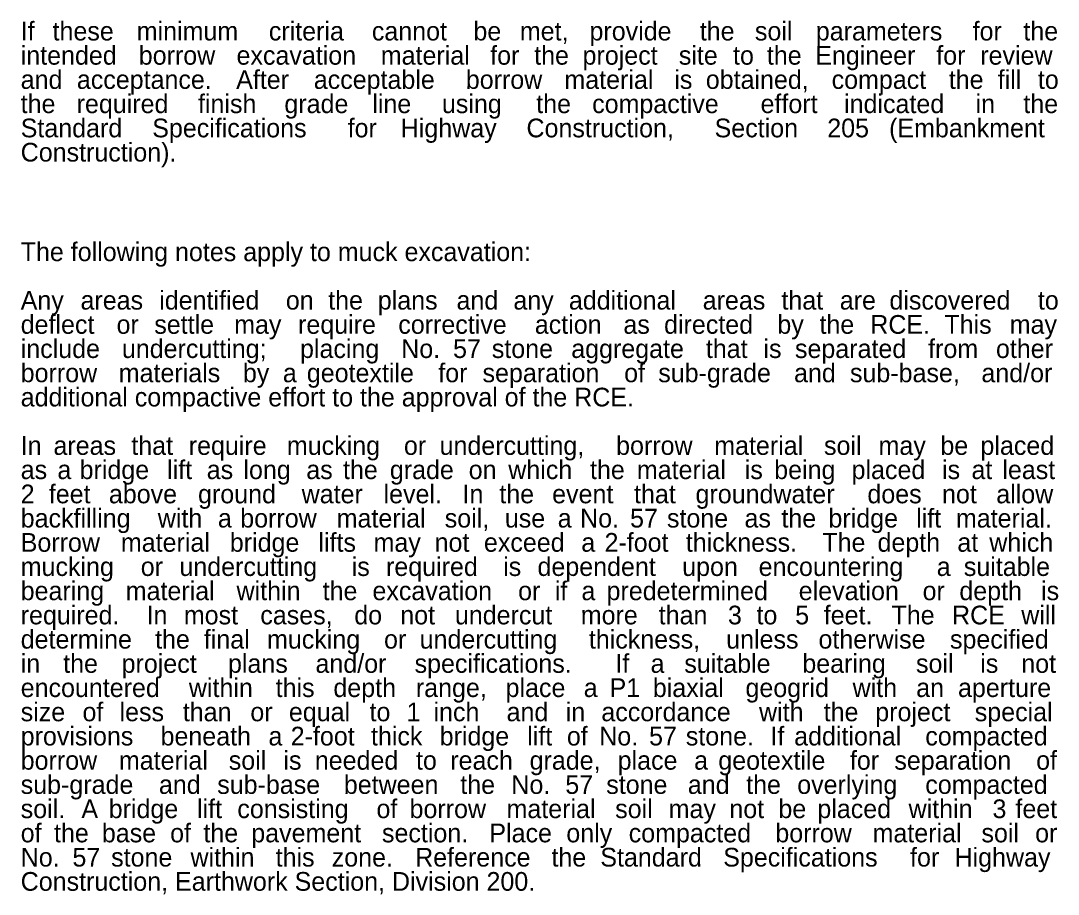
# Model space of a CAD drawing. Extents: x 4804 to 5434, y 4929 to 5221.
# Drawn here: x 5102.6 to 5179.4, y 5037.3 to 5101.9 of the extents above; entities that cross this region are included whole.
import ezdxf

# ---------------------------------------------------------------- set-up
doc = ezdxf.new("R2010")
doc.units = 0
doc.layers.add('RD_TX_RoadID', color=7, linetype='Continuous')

msp = doc.modelspace()

# ---------------------------------------------------------------- texts
at = {"layer": 'RD_TX_RoadID'}
for s, p in [('If ', (5102.645, 5100.425)), ('these ', (5105.003, 5100.425)), ('minimum ', (5111.231, 5100.425)), ('criteria ', (5121.007, 5100.425)), ('be ', (5136.149, 5100.425)), ('provide ', (5144.737, 5100.425)), ('the ', (5152.899, 5100.425)), ('soil ', (5156.977, 5100.425)), ('for ', (5173.09, 5100.425)), ('the ', (5176.845, 5100.425)), ('cannot ', (5128.632, 5100.425)), ('met, ', (5139.583, 5100.425)), ('parameters ', (5161.486, 5100.425)), ('intended ', (5102.645, 5098.633)), ('borrow ', (5111.383, 5098.633)), ('excavation ', (5118.617, 5098.633)), ('material ', (5129.292, 5098.633)), ('for ', (5137.387, 5098.633)), ('the ', (5140.643, 5098.633)), ('project ', (5144.223, 5098.633)), ('site ', (5151.349, 5098.633)), ('to ', (5155.359, 5098.633)), ('the ', (5157.863, 5098.633)), ('Engineer ', (5161.443, 5098.633)), ('for ', (5170.398, 5098.633)), ('review ', (5173.654, 5098.633)), ('and ', (5102.645, 5096.842)), ('acceptance. ', (5106.801, 5096.842)), ('After ', (5118.59, 5096.842)), (' acceptable ', (5123.82, 5096.842)), (' borrow ', (5135.07, 5096.842)), ('material ', (5142.88, 5096.842)), ('is ', (5151.013, 5096.842)), ('obtained, ', (5153.343, 5096.842)), ('compact ', (5162.656, 5096.842)), ('the ', (5171.326, 5096.842)), ('fill ', (5174.944, 5096.842)), ('to ', (5177.917, 5096.842)), ('the ', (5102.645, 5095.05)), ('required ', (5106.785, 5095.05)), ('finish ', (5115.763, 5095.05)), ('grade ', (5122.159, 5095.05)), ('line ', (5128.665, 5095.05)), ('using ', (5133.817, 5095.05)), ('the ', (5140.795, 5095.05)), ('compactive ', (5144.935, 5095.05)), ('effort ', (5157.396, 5095.05)), ('indicated ', (5163.576, 5095.05)), ('in ', (5173.305, 5095.05)), ('the ', (5176.844, 5095.05)), ('Standard ', (5102.645, 5093.258)), ('Specifications ', (5112.379, 5093.258)), ('for ', (5126.841, 5093.258)), ('Highway ', (5130.769, 5093.258)), ('Construction, ', (5140.073, 5093.258)), ('Section ', (5153.995, 5093.258)), ('205 ', (5162.331, 5093.258)), ('(Embankment ', (5166.907, 5093.258)), ('Construction).', (5102.645, 5091.466)), ('The following notes apply to muck excavation:', (5102.645, 5084.097)), ('Any ', (5102.645, 5080.513)), ('identified ', (5112.897, 5080.513)), ('the ', (5125.399, 5080.513)), ('plans ', (5129.072, 5080.513)), ('and ', (5134.896, 5080.513)), ('additional ', (5143.211, 5080.513)), ('that ', (5158.942, 5080.513)), ('discovered ', (5166.933, 5080.513)), ('areas ', (5107.071, 5080.513)), ('on ', (5122.264, 5080.513)), ('any ', (5139.107, 5080.513)), ('areas ', (5153.116, 5080.513)), ('are ', (5163.258, 5080.513)), ('to ', (5177.917, 5080.513)), ('deflect ', (5102.645, 5078.722)), ('or ', (5109.737, 5078.722)), ('settle ', (5112.531, 5078.722)), ('may ', (5118.441, 5078.722)), ('require ', (5123.171, 5078.722)), ('corrective ', (5130.587, 5078.722)), ('action ', (5140.691, 5078.722)), ('as ', (5147.246, 5078.722)), ('directed ', (5150.256, 5078.722)), ('by ', (5158.639, 5078.722)), ('the ', (5161.756, 5078.722)), ('RCE. ', (5165.516, 5078.722)), ('This ', (5170.998, 5078.722)), ('may ', (5175.834, 5078.722)), ('include ', (5102.645, 5076.93)), ('undercutting; ', (5110.134, 5076.93)), ('placing ', (5123.316, 5076.93)), ('No. ', (5130.805, 5076.93)), ('57 ', (5134.64, 5076.93)), ('stone ', (5137.509, 5076.93)), ('aggregate ', (5143.386, 5076.93)), ('that ', (5153.348, 5076.93)), ('is ', (5157.611, 5076.93)), ('separated ', (5159.942, 5076.93)), ('from ', (5169.797, 5076.93)), ('other ', (5174.814, 5076.93)), ('borrow ', (5102.645, 5075.138)), ('materials ', (5109.899, 5075.138)), ('by ', (5119.09, 5075.138)), ('geotextile ', (5123.82, 5075.138)), ('for ', (5133.546, 5075.138)), ('separation ', (5136.822, 5075.138)), ('of ', (5147.301, 5075.138)), ('sub-grade ', (5149.826, 5075.138)), ('and ', (5159.874, 5075.138)), ('sub-base, ', (5164.012, 5075.138)), ('and/or ', (5173.739, 5075.138)), ('a ', (5122.046, 5075.138)), ('additional compactive effort to the approval of the RCE. ', (5102.645, 5073.346)), ('In ', (5102.645, 5069.762)), ('that ', (5110.83, 5069.762)), ('require ', (5115.081, 5069.762)), ('mucking ', (5122.344, 5069.762)), ('undercutting, ', (5133.644, 5069.762)), ('borrow ', (5146.707, 5069.762)), ('material ', (5153.968, 5069.762)), ('soil ', (5162.091, 5069.762)), ('be ', (5170.706, 5069.762)), ('placed ', (5173.669, 5069.762)), ('areas ', (5105.07, 5069.762)), ('or ', (5131.004, 5069.762)), ('may ', (5166.129, 5069.762)), ('as ', (5102.645, 5067.971)), ('a ', (5105.363, 5067.971)), ('bridge ', (5107.005, 5067.971)), ('lift ', (5113.482, 5067.971)), ('as ', (5116.411, 5067.971)), ('long ', (5119.128, 5067.971)), ('as ', (5123.778, 5067.971)), ('the ', (5126.496, 5067.971)), ('grade ', (5129.963, 5067.971)), ('on ', (5135.797, 5067.971)), ('which ', (5138.728, 5067.971)), ('the ', (5144.776, 5067.971)), ('material ', (5148.244, 5067.971)), ('is ', (5156.227, 5067.971)), ('being ', (5158.406, 5067.971)), ('placed ', (5164.131, 5067.971)), ('is ', (5170.825, 5067.971)), ('at ', (5173.004, 5067.971)), ('least ', (5175.29, 5067.971)), ('2 ', (5102.645, 5066.179)), ('feet ', (5104.727, 5066.179)), ('above ', (5109.172, 5066.179)), ('ground ', (5115.769, 5066.179)), ('water ', (5123.437, 5066.179)), ('level. ', (5129.496, 5066.179)), ('In ', (5135.34, 5066.179)), ('the ', (5138.065, 5066.179)), ('event ', (5141.973, 5066.179)), ('that ', (5148.031, 5066.179)), ('groundwater ', (5152.583, 5066.179)), ('does ', (5165.303, 5066.179)), ('not ', (5170.824, 5066.179)), ('allow ', (5174.838, 5066.179)), ('backfilling ', (5102.645, 5064.387)), ('with ', (5112.789, 5064.387)), ('borrow ', (5118.893, 5064.387)), ('material ', (5126.028, 5064.387)), ('soil, ', (5134.025, 5064.387)), ('No. ', (5144.042, 5064.387)), ('57 ', (5147.739, 5064.387)), ('the ', (5158.939, 5064.387)), ('bridge ', (5162.42, 5064.387)), ('lift ', (5168.911, 5064.387)), ('material. ', (5171.853, 5064.387)), ('a ', (5117.237, 5064.387)), ('use ', (5138.474, 5064.387)), ('a ', (5142.387, 5064.387)), ('stone ', (5150.47, 5064.387)), ('as ', (5156.208, 5064.387)), ('Borrow ', (5102.645, 5062.595)), ('material ', (5110.06, 5062.595)), ('bridge ', (5118.121, 5062.595)), ('lifts ', (5124.677, 5062.595)), ('may ', (5128.758, 5062.595)), ('not ', (5133.274, 5062.595)), ('exceed ', (5136.926, 5062.595)), ('a ', (5144.129, 5062.595)), ('2-foot ', (5145.849, 5062.595)), ('thickness. ', (5151.864, 5062.595)), ('The ', (5161.967, 5062.595)), ('depth ', (5166.05, 5062.595)), ('at ', (5171.96, 5062.595)), ('which ', (5174.324, 5062.595)), ('mucking ', (5102.645, 5060.803)), ('or ', (5111.528, 5060.803)), ('undercutting ', (5114.391, 5060.803)), ('is ', (5127.139, 5060.803)), ('required ', (5129.68, 5060.803)), ('is ', (5138.348, 5060.803)), ('dependent ', (5140.889, 5060.803)), ('upon ', (5151.597, 5060.803)), ('encountering ', (5157.254, 5060.803)), ('a ', (5170.433, 5060.803)), ('suitable ', (5172.438, 5060.803)), ('bearing ', (5102.645, 5059.011)), ('material ', (5110.416, 5059.011)), ('within ', (5118.617, 5059.011)), ('the ', (5124.988, 5059.011)), ('excavation ', (5128.674, 5059.011)), ('if ', (5142.174, 5059.011)), ('predetermined ', (5146, 5059.011)), ('elevation ', (5160.219, 5059.011)), ('depth ', (5172.106, 5059.011)), ('is ', (5178.155, 5059.011)), ('or ', (5139.455, 5059.011)), ('a ', (5144.14, 5059.011)), ('or ', (5169.387, 5059.011)), ('required. ', (5102.645, 5057.22)), ('In ', (5111.959, 5057.22)), ('most ', (5114.717, 5057.22)), ('cases, ', (5120.377, 5057.22)), ('do ', (5127.329, 5057.22)), ('not ', (5130.732, 5057.22)), ('undercut ', (5134.778, 5057.22)), ('more ', (5144.091, 5057.22)), ('than ', (5149.86, 5057.22)), ('3 ', (5154.981, 5057.22)), ('to ', (5157.095, 5057.22)), ('5 ', (5159.96, 5057.22)), ('feet. ', (5162.074, 5057.22)), ('The ', (5167.088, 5057.22)), ('RCE ', (5171.566, 5057.22)), ('will ', (5176.689, 5057.22)), ('determine ', (5102.645, 5055.428)), ('the ', (5112.591, 5055.428)), ('final ', (5116.196, 5055.428)), ('mucking ', (5120.874, 5055.428)), ('or ', (5129.531, 5055.428)), ('undercutting ', (5132.168, 5055.428)), ('thickness, ', (5144.69, 5055.428)), ('unless ', (5154.852, 5055.428)), ('otherwise ', (5161.682, 5055.428)), ('specified ', (5171.413, 5055.428)), ('in ', (5102.645, 5053.636)), ('the ', (5105.788, 5053.636)), ('project ', (5110.113, 5053.636)), ('plans ', (5117.985, 5053.636)), ('and/or ', (5124.46, 5053.636)), ('specifications. ', (5131.795, 5053.636)), ('If ', (5146.652, 5053.636)), ('suitable ', (5151.756, 5053.636)), ('bearing ', (5160.488, 5053.636)), ('soil ', (5168.898, 5053.636)), ('is ', (5173.653, 5053.636)), ('a ', (5149.257, 5053.636)), ('not ', (5176.689, 5053.636)), ('encountered ', (5102.645, 5051.844)), ('within ', (5115.089, 5051.844)), ('this ', (5121.512, 5051.844)), ('depth ', (5125.786, 5051.844)), ('range, ', (5131.888, 5051.844)), ('place ', (5138.528, 5051.844)), ('a ', (5144.31, 5051.844)), ('P1 ', (5146.222, 5051.844)), ('biaxial ', (5149.424, 5051.844)), ('geogrid ', (5156.28, 5051.844)), ('with ', (5164.209, 5051.844)), ('an ', (5168.913, 5051.844)), ('aperture ', (5172.007, 5051.844)), ('size ', (5102.645, 5050.052)), ('of ', (5107.217, 5050.052)), ('less ', (5109.96, 5050.052)), ('than ', (5114.64, 5050.052)), ('or ', (5119.639, 5050.052)), ('equal ', (5122.49, 5050.052)), ('to ', (5128.459, 5050.052)), ('1 ', (5131.201, 5050.052)), ('inch ', (5133.193, 5050.052)), (' and ', (5138.086, 5050.052)), ('in ', (5142.979, 5050.052)), ('accordance ', (5145.615, 5050.052)), ('with ', (5157.282, 5050.052)), ('the ', (5162.066, 5050.052)), ('project ', (5165.884, 5050.052)), ('special ', (5173.248, 5050.052)), ('provisions ', (5102.645, 5048.261)), ('beneath ', (5112.995, 5048.261)), ('2-foot ', (5122.626, 5048.261)), ('thick ', (5128.567, 5048.261)), ('bridge ', (5133.65, 5048.261)), ('lift ', (5140.131, 5048.261)), ('of ', (5143.063, 5048.261)), ('No. ', (5145.458, 5048.261)), ('57 ', (5149.145, 5048.261)), ('If ', (5158.131, 5048.261)), ('additional ', (5159.882, 5048.261)), ('compacted ', (5169.585, 5048.261)), ('a ', (5120.981, 5048.261)), ('stone. ', (5151.866, 5048.261)), ('borrow ', (5102.645, 5046.469)), ('material ', (5109.913, 5046.469)), ('soil ', (5118.042, 5046.469)), ('is ', (5122.086, 5046.469)), ('needed ', (5124.411, 5046.469)), ('to ', (5131.895, 5046.469)), ('reach ', (5134.433, 5046.469)), ('grade, ', (5140.306, 5046.469)), ('place ', (5146.822, 5046.469)), ('a ', (5152.48, 5046.469)), ('geotextile ', (5154.268, 5046.469)), ('for ', (5164.007, 5046.469)), ('separation ', (5167.297, 5046.469)), ('of ', (5177.79, 5046.469)), ('sub-grade ', (5102.645, 5044.677)), ('and ', (5112.873, 5044.677)), ('sub-base ', (5117.19, 5044.677)), ('between ', (5126.559, 5044.677)), ('the ', (5135.175, 5044.677)), ('No. ', (5138.954, 5044.677)), ('57 ', (5142.948, 5044.677)), ('stone ', (5145.977, 5044.677)), ('and ', (5152.013, 5044.677)), ('the ', (5156.33, 5044.677)), ('overlying ', (5160.109, 5044.677)), ('compacted ', (5169.585, 5044.677)), ('soil. ', (5102.645, 5042.885)), ('A ', (5107.137, 5042.885)), ('bridge ', (5109.158, 5042.885)), ('lift ', (5115.692, 5042.885)), ('consisting ', (5118.677, 5042.885)), ('of ', (5128.972, 5042.885)), ('borrow ', (5131.421, 5042.885)), ('material ', (5138.599, 5042.885)), ('soil ', (5146.639, 5042.885)), ('be ', (5158.719, 5042.885)), ('placed ', (5161.6, 5042.885)), ('within ', (5168.35, 5042.885)), ('3 ', (5174.56, 5042.885)), ('feet ', (5176.259, 5042.885)), ('may ', (5150.594, 5042.885)), ('not ', (5155.088, 5042.885)), ('of ', (5102.645, 5041.093)), ('the ', (5105.111, 5041.093)), ('base ', (5108.653, 5041.093)), ('of ', (5113.702, 5041.093)), ('the ', (5116.168, 5041.093)), ('pavement ', (5119.709, 5041.093)), ('section. ', (5129.379, 5041.093)), ('Place ', (5137.327, 5041.093)), ('only ', (5143.022, 5041.093)), ('compacted ', (5147.639, 5041.093)), ('borrow ', (5158.49, 5041.093)), ('material ', (5165.686, 5041.093)), ('soil ', (5173.743, 5041.093)), ('or ', (5177.715, 5041.093)), ('No. ', (5102.645, 5039.301)), ('57 ', (5106.475, 5039.301)), ('stone ', (5109.339, 5039.301)), ('within ', (5115.211, 5039.301)), ('this ', (5121.511, 5039.301)), ('zone. ', (5125.663, 5039.301)), (' Reference ', (5131.32, 5039.301)), ('the ', (5141.923, 5039.301)), ('Standard ', (5145.537, 5039.301)), ('Specifications ', (5154.634, 5039.301)), ('for ', (5168.459, 5039.301)), ('Highway ', (5171.751, 5039.301)), ('Construction, Earthwork Section, Division 200. ', (5102.645, 5037.51))]:
    msp.add_text(s, height=1.3845, dxfattribs=at).set_placement(p)

doc.saveas('drawing.dxf')
